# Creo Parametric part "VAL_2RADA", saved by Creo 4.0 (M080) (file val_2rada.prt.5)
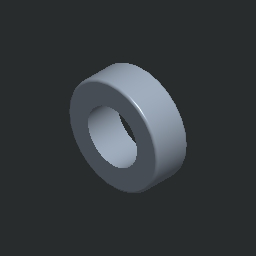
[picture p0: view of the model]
Units: millimeter Kilogram Sec (mmKs); MM, KILOGRAM, SECS
Materials in the file: OCEL_N

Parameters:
  MFG_WP_MATERIAL = "RO6_2"
  NAZOV = "VAL_2RADA"
  PTC_MATERIAL_NAME = "OCEL_N"

Other parameters: HMOTNOST, HUSTOTA

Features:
  1. round
  2. datum plane "DTM1"
  3. cut

Named dimensions: velke_D

Layers: 1, 2, 3, 4, 5, 6, 7, 8, 9, 10, 11, 12, 13, 14, 15, 16, 17, 18, 19, 20, 21, 22, 23, 24, 25, 26, 27, 28, 29, 30, 31, 32

Family table entries: GENERIC, LOZISKO_NN3006K, VAL_2RADA, value(d_val), 2/3, value(i_val), LOZISKO_NN3007K, VAL_2RADA, 2/O, 2/4, LOZISKO_NN3008K, VAL_2RADA, !/D, 2/Q, 2/5, LOZISKO_NN3009K, VAL_2RADA, 2/7, LOZISKO_NN3010K, VAL_2RADA, !/I, 2/T, 2/7, LOZISKO_NN3011K, VAL_2RADA, 2/:, LOZISKO_NN3012K, VAL_2RADA, !/N, 2/:, LOZISKO_NN3013K, VAL_2RADA, 2/Y, 2/:, LOZISKO_NN3014K, VAL_2RADA, 2/>, LOZISKO_NN3015K, VAL_2RADA, 2/>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

Surfaces: 4 torus, 2 plane, 2 cone, 1 cylinder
